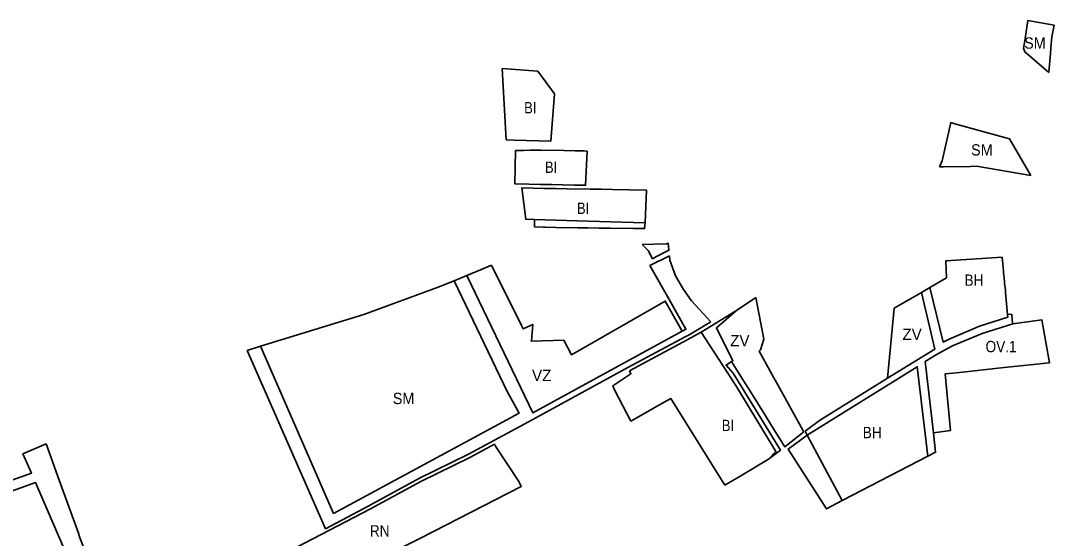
# Model space of a CAD drawing. Extents: x -650971 to -642489, y -1074311 to -1062745.
# Drawn here: x -648968 to -647874, y -1070700 to -1070152 of the extents above; entities that cross this region are included whole.
import ezdxf

# ---------------------------------------------------------------- set-up
doc = ezdxf.new("R2010")
doc.units = 0
doc.header["$LTSCALE"] = 4.8
for name, color, linetype, lineweight in [('1', 7, 'Continuous', 35), ('11', 7, 'Continuous', 35), ('15', 7, 'Continuous', 35), ('18', 7, 'Continuous', 35), ('2', 7, 'Continuous', 35), ('36', 7, 'Continuous', 35), ('40', 7, 'Continuous', 35), ('48', 7, 'Continuous', 35), ('62', 7, 'Continuous', 35), ('7', 7, 'Continuous', 35)]:
    doc.layers.add(name, color=color, linetype=linetype, lineweight=lineweight)

msp = doc.modelspace()

# ---------------------------------------------------------------- linework, layer by layer
at = {"layer": '1'}
for points in [[(-648005.668, -1070434.146), (-647988.11, -1070423.93), (-647988.86, -1070405.95), (-647929.24, -1070401.97)], [(-647929.24, -1070401.97), (-647927.73, -1070416.98), (-647927.67, -1070418.74), (-647927.08, -1070424.28), (-647926.69, -1070428.19), (-647926.53, -1070429.76), (-647925.74, -1070436.62), (-647925.5, -1070439.63), (-647925.02, -1070447.29), (-647924.63, -1070451.09), (-647923.53, -1070462.75)], [(-647923.53, -1070462.75), (-647923.247, -1070465.749), (-647953.251, -1070475.276), (-647985.19, -1070488.804), (-647991.539, -1070492.016), (-648005.668, -1070434.146)]]:
    msp.add_lwpolyline(points, dxfattribs=at)
msp.add_lwpolyline([(-648135.47, -1070590.61), (-648019, -1070518), (-648007.838, -1070612.851), (-648098.637, -1070659.682)], close=True, dxfattribs=at)
at = {"layer": '11'}
for points in [[(-647917.98, -1070472.47), (-647899.87, -1070470.04), (-647887.08, -1070468.54), (-647879.16, -1070513.83), (-647879.89, -1070513.91)], [(-648002, -1070588), (-648010.831, -1070512.588), (-647999.756, -1070505.655), (-647990.295, -1070500.352), (-647981.81, -1070496.06), (-647950.48, -1070482.79), (-647917.98, -1070472.47)], [(-647879.89, -1070513.91), (-647886.09, -1070514.58), (-647889.27, -1070514.92), (-647927.14, -1070519), (-647977.41, -1070524.43), (-647989.5, -1070525.73), (-647984.03, -1070585.46), (-648002, -1070588)]]:
    msp.add_lwpolyline(points, dxfattribs=at)
at = {"layer": '15'}
for p, q in [((-648247.67, -1070481.57), (-648210.48, -1070458.42)), ((-648728.255, -1070500.709), (-648714.161, -1070496.376)), ((-648135.47, -1070590.61), (-648098.637, -1070659.682))]:
    msp.add_line(p, q, dxfattribs=at)
for points in [[(-648424.31, -1070362.21), (-648412.88, -1070362.55), (-648401.36, -1070362.89), (-648378.49, -1070363.57), (-648367.26, -1070363.9), (-648355.27, -1070364.25), (-648343.31, -1070364.61), (-648331.32, -1070364.96), (-648319.33, -1070365.32), (-648307.13, -1070365.57), (-648307.67, -1070371.78)], [(-648307.67, -1070371.78), (-648310.85, -1070371.8), (-648319.67, -1070371.65), (-648343.67, -1070371.41), (-648355.67, -1070371.28), (-648367.67, -1070371.16), (-648378.73, -1070370.94), (-648401.35, -1070370.5), (-648412.75, -1070370.28), (-648414.75, -1070370.24), (-648424.05, -1070370), (-648424.31, -1070362.21)], [(-648331.32, -1070364.96), (-648343.31, -1070364.61), (-648355.27, -1070364.25), (-648367.26, -1070363.9), (-648378.49, -1070363.57), (-648401.36, -1070362.89), (-648412.88, -1070362.55), (-648424.31, -1070362.21), (-648424.05, -1070370)], [(-648424.05, -1070370), (-648414.75, -1070370.24), (-648412.75, -1070370.28), (-648401.35, -1070370.5), (-648378.73, -1070370.94), (-648367.67, -1070371.16), (-648355.67, -1070371.28), (-648343.67, -1070371.41), (-648319.67, -1070371.65)], [(-648319.67, -1070371.65), (-648310.85, -1070371.8), (-648307.67, -1070371.78), (-648307.13, -1070365.57), (-648319.33, -1070365.32), (-648331.32, -1070364.96)], [(-648310.275, -1070388.476), (-648284.37, -1070387.85), (-648282.582, -1070387.276), (-648281.907, -1070394.762)], [(-648282.582, -1070387.276), (-648284.37, -1070387.85), (-648310.275, -1070388.476)], [(-648299.32, -1070403.93), (-648303.705, -1070395.035), (-648310.275, -1070388.476)], [(-648310.275, -1070388.476), (-648303.705, -1070395.035), (-648299.32, -1070403.93)], [(-648299.32, -1070403.93), (-648295.18, -1070401.23), (-648281.907, -1070394.762), (-648282.582, -1070387.276)], [(-648267.801, -1070480.55), (-648263.859, -1070478.393), (-648282.01, -1070446.35), (-648302.01, -1070411.05), (-648281.388, -1070400.523)], [(-648281.907, -1070394.762), (-648295.18, -1070401.23), (-648299.32, -1070403.93)], [(-648281.388, -1070400.523), (-648280.974, -1070405.11), (-648274.808, -1070421.647), (-648266.416, -1070436.404), (-648257.96, -1070448.17), (-648237.475, -1070470.361)], [(-648714.161, -1070496.376), (-648636.757, -1070673.431), (-648440.531, -1070567.236), (-648452.97, -1070544.21), (-648509.227, -1070426.957), (-648495.666, -1070421.476)], [(-648495.666, -1070421.476), (-648425.835, -1070567.021), (-648267.801, -1070480.55)], [(-648050.38, -1070530.2), (-648000.442, -1070499.336), (-648014.63, -1070439.36), (-648005.668, -1070434.146)], [(-648005.668, -1070434.146), (-647991.539, -1070492.016), (-647985.19, -1070488.804), (-647953.251, -1070475.276), (-647923.247, -1070465.749), (-647923.53, -1070462.75), (-647918.95, -1070462.36)], [(-648210.48, -1070458.42), (-648231.53, -1070476.99), (-648214.34, -1070511.86), (-648215.48, -1070512.59)], [(-647918.95, -1070462.36), (-647918.54, -1070468.61), (-647917.98, -1070472.47)], [(-648237.475, -1070470.361), (-648260.57, -1070484.2), (-648264.56, -1070486.34), (-648325.21, -1070518.84), (-648415.08, -1070568.07), (-648434.43, -1070578.53), (-648494.04, -1070610.73), (-648545.76, -1070636.22), (-648599.66, -1070665.32), (-648645.331, -1070689.546), (-648728.255, -1070500.709)], [(-647917.98, -1070472.47), (-647950.48, -1070482.79), (-647981.81, -1070496.06), (-647990.295, -1070500.352), (-647999.756, -1070505.655), (-648010.831, -1070512.588), (-648002, -1070588)], [(-648176.54, -1070616.09), (-648168.575, -1070607.847), (-648211, -1070538), (-648247.67, -1070481.57)], [(-648215.48, -1070512.59), (-648221.359, -1070516.349), (-648213.87, -1070524.8), (-648163.8, -1070606.27), (-648169.28, -1070610.49), (-648176.54, -1070616.09)], [(-648007.838, -1070612.851), (-648019, -1070518), (-648135.47, -1070590.61), (-648137.78, -1070586.25)], [(-648137.78, -1070586.25), (-648122.57, -1070575), (-648050.38, -1070530.2)], [(-648002, -1070588), (-647999.588, -1070608.596), (-648007.838, -1070612.851)], [(-648098.637, -1070659.682), (-648115.057, -1070668.651), (-648155.582, -1070605.295), (-648135.47, -1070590.61)]]:
    msp.add_lwpolyline(points, dxfattribs=at)
at = {"layer": '18'}
for points in [[(-647905.17, -1070184.5), (-647906.6, -1070180.65), (-647905.28, -1070172.86), (-647902.17, -1070151.64), (-647873.97, -1070156.58)], [(-647873.97, -1070156.58), (-647876.74, -1070168.88), (-647877.68, -1070180.34), (-647878.18, -1070186.33), (-647879.81, -1070206.08), (-647879.839, -1070206.461)], [(-647879.839, -1070206.461), (-647905.08, -1070184.73), (-647905.17, -1070184.5)], [(-647995.46, -1070306.55), (-647992.71, -1070300.01), (-647983.6, -1070259.5), (-647979.24, -1070260.71), (-647921.51, -1070276.76), (-647898.82, -1070315.51)], [(-647898.82, -1070315.51), (-647956.36, -1070305.77), (-647962.82, -1070305.9), (-647991.12, -1070306.46), (-647995.46, -1070306.55)], [(-648714.161, -1070496.376), (-648604.92, -1070462.79), (-648526.28, -1070433.85), (-648509.227, -1070426.957)], [(-648509.227, -1070426.957), (-648452.97, -1070544.21), (-648440.531, -1070567.236), (-648636.757, -1070673.431), (-648714.161, -1070496.376)]]:
    msp.add_lwpolyline(points, dxfattribs=at)
at = {"layer": '2'}
msp.add_line((-648458.28, -1070202.26), (-648420.7, -1070204.96), dxfattribs=at)
for points in [[(-648406.8, -1070279.32), (-648446.18, -1070278.15), (-648454.038, -1070277.766), (-648458.28, -1070202.26)], [(-648420.7, -1070204.96), (-648403.04, -1070229.15), (-648406.8, -1070279.32)], [(-648424.31, -1070362.21), (-648433.46, -1070361.94), (-648437.65, -1070328.8), (-648425.43, -1070329), (-648413.45, -1070329.19), (-648401.41, -1070329.39), (-648389.43, -1070329.58), (-648365.35, -1070329.98), (-648353.32, -1070330.23), (-648341.46, -1070330.48), (-648305.47, -1070331.23), (-648307.13, -1070365.57)], [(-648307.13, -1070365.57), (-648319.33, -1070365.32), (-648331.32, -1070364.96), (-648343.31, -1070364.61), (-648355.27, -1070364.25), (-648367.26, -1070363.9), (-648378.49, -1070363.57), (-648401.36, -1070362.89), (-648412.88, -1070362.55), (-648424.31, -1070362.21)], [(-648323.59, -1070522.48), (-648262.69, -1070489.67), (-648247.67, -1070481.57)], [(-648247.67, -1070481.57), (-648211, -1070538), (-648168.575, -1070607.847), (-648176.54, -1070616.09)], [(-648322.16, -1070575.76), (-648339.33, -1070542.45), (-648341.41, -1070538.42), (-648322.18, -1070525.44), (-648323.59, -1070522.48)], [(-648222.58, -1070643.48), (-648279.736, -1070551.783), (-648289.22, -1070557.15), (-648322.16, -1070575.76)], [(-648176.54, -1070616.09), (-648205.74, -1070633.46), (-648222.58, -1070643.48)]]:
    msp.add_lwpolyline(points, dxfattribs=at)
msp.add_lwpolyline([(-648368.25, -1070289.71), (-648370.07, -1070325.94), (-648382.06, -1070325.7), (-648394.08, -1070325.47), (-648406.09, -1070325.23), (-648418.1, -1070325), (-648430.02, -1070324.76), (-648444.85, -1070324.47), (-648444.15, -1070289.16), (-648435.93, -1070288.95), (-648428.98, -1070288.92), (-648420.39, -1070288.79), (-648416.93, -1070288.85), (-648392.94, -1070289.25), (-648380.97, -1070289.44), (-648372.1, -1070289.59)], close=True, dxfattribs=at)
at = {"layer": '36'}
for points in [[(-648495.666, -1070421.476), (-648481.18, -1070415.62), (-648469.77, -1070410.47)], [(-648469.77, -1070410.47), (-648437.97, -1070474.49), (-648436.22, -1070478.01), (-648426.05, -1070473.34), (-648427.06, -1070486.49), (-648427.41, -1070491.08), (-648393.14, -1070490.07), (-648385.085, -1070505.351), (-648285.75, -1070448.49), (-648267.801, -1070480.55)], [(-648267.801, -1070480.55), (-648425.835, -1070567.021), (-648495.666, -1070421.476)]]:
    msp.add_lwpolyline(points, dxfattribs=at)
at = {"layer": '40'}
for points in [[(-648215.48, -1070512.59), (-648214.34, -1070511.86), (-648231.53, -1070476.99), (-648210.48, -1070458.42), (-648189.93, -1070444.71)], [(-648189.93, -1070444.71), (-648181.386, -1070488.724), (-648184.791, -1070500.073), (-648186.441, -1070501.65), (-648178.7, -1070515.58), (-648172.96, -1070525.9), (-648170.72, -1070529.92), (-648166.63, -1070537.28), (-648140.05, -1070585.09), (-648138.93, -1070587.1)], [(-648050.38, -1070530.2), (-648043.43, -1070456.12), (-648014.63, -1070439.36)], [(-648014.63, -1070439.36), (-648000.442, -1070499.336), (-648050.38, -1070530.2)], [(-648138.93, -1070587.1), (-648159.23, -1070602.75), (-648171.02, -1070583.86), (-648182.98, -1070564.68), (-648190.71, -1070552.3), (-648197.59, -1070541.27), (-648203.83, -1070531.25), (-648210.19, -1070521.07), (-648215.48, -1070512.59)]]:
    msp.add_lwpolyline(points, dxfattribs=at)
at = {"layer": '48'}
for points in [[(-649050.081, -1070663.981), (-648956.687, -1070630.825), (-648965.569, -1070610.382), (-648941.064, -1070599.735)], [(-648941.064, -1070599.735), (-648927.141, -1070638.141), (-648906.79, -1070694.25), (-648905.65, -1070698.06), (-648892.215, -1070733.293)], [(-649025.129, -1070754.377), (-648924.668, -1070712.022), (-648922.196, -1070710.207), (-648952.455, -1070640.564), (-649047.11, -1070674.743), (-649050.081, -1070663.981)]]:
    msp.add_lwpolyline(points, dxfattribs=at)
at = {"layer": '7'}
for points in [[(-648693.45, -1070718.46), (-648597.74, -1070668.62), (-648544.42, -1070639.42), (-648492.47, -1070614.2), (-648466.61, -1070600.21)], [(-648466.61, -1070600.21), (-648465.28, -1070602.24), (-648440.8, -1070639.72), (-648438.13, -1070644.73), (-648544.906, -1070699.451), (-648574.27, -1070714.5)]]:
    msp.add_lwpolyline(points, dxfattribs=at)

# ---------------------------------------------------------------- texts
at = {"layer": '62'}
for s, width, p in [('SM', 0.95, (-647905.887, -1070181.298)), ('BI', 0.85, (-648435.024, -1070249.825)), ('SM', 0.95, (-647962.077, -1070294.464)), ('BI', 0.85, (-648413.024, -1070312.825)), ('BI', 0.85, (-648379.14, -1070356.31)), ('BH', 0.9, (-647969.069, -1070432.39)), ('OV.1', 0.9, (-647946.769, -1070502.709)), ('SM', 0.95, (-648574.138, -1070557.646)), ('BI', 0.85, (-648225.838, -1070586.256)), ('BH', 0.9, (-648076.769, -1070593.709)), ('RN', 0.9, (-648598.428, -1070697.883))]:
    msp.add_text(s, height=12, dxfattribs=dict(at, width=width)).set_placement(p)
for s, p in [('ZV', (-648034.769, -1070489.709)), ('ZV', (-648217.069, -1070496.39)), ('VZ', (-648426.778, -1070533.286))]:
    msp.add_text(s, height=12, dxfattribs=at).set_placement(p)

doc.saveas('drawing.dxf')
